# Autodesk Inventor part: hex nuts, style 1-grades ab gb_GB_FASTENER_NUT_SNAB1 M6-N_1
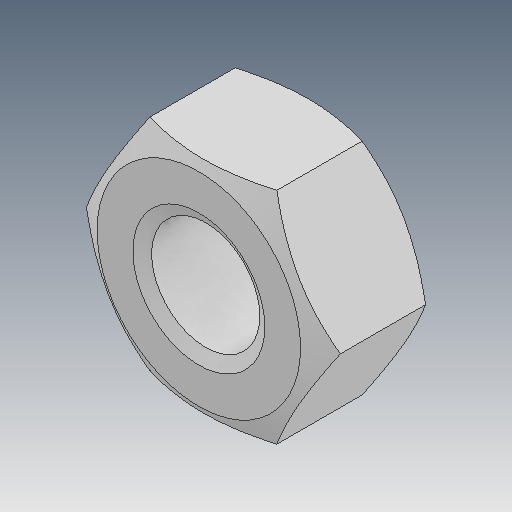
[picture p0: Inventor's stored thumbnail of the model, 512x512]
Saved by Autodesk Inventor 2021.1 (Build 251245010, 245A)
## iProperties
Created: 2019-04
Part Number: hex nuts, style 1-grades ab gb_GB_FASTENER_NUT_SNAB1 M6-N_1
Material: Ogólny
Document SubType Name: Modeling
Designer: user
Density: 1 g/cm^3
Appearance: Domyślna
Author: user
Revision Number: ÈÎºÎ
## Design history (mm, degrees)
feature "ÊäÈë1"
node "Bryła1"
